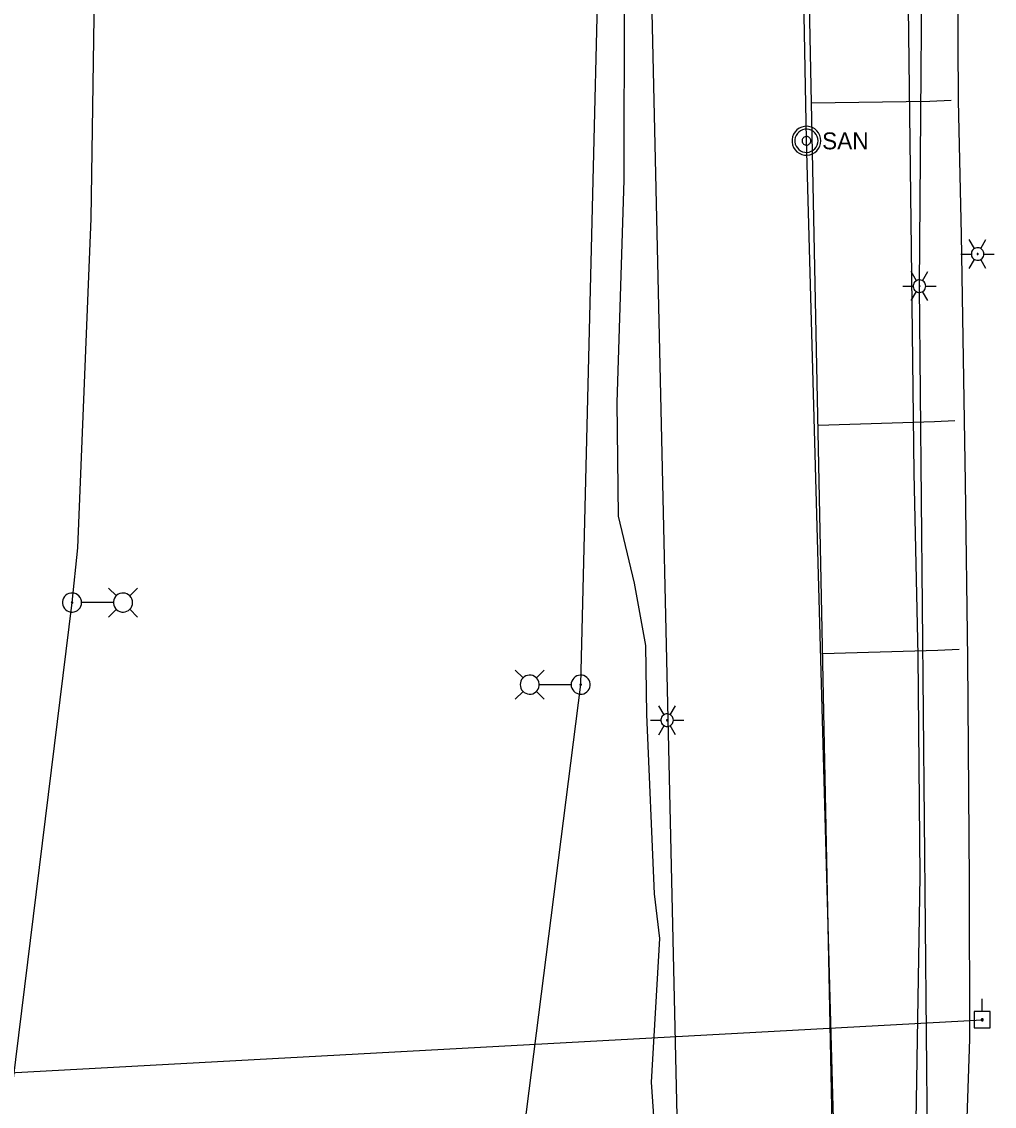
# Model space of a CAD drawing. Extents: x 596028 to 606371, y 330010 to 403088.
# Drawn here: x 604862.3 to 605083.6, y 331870.6 to 332117.3 of the extents above; entities that cross this region are included whole.
import ezdxf

# ---------------------------------------------------------------- set-up
doc = ezdxf.new("R2010")
doc.units = 0
for name, color, linetype in [('E_LTG', 7, 'Continuous'), ('E_LTG_CID', 7, 'Continuous'), ('E_UTL_E_UG', 7, 'Continuous'), ('E_UTL_EPowerPole', 7, 'Continuous'), ('E_UTL_G_UG', 7, 'Continuous'), ('E_UTL_Overhead', 7, 'Continuous'), ('E_UTL_SAN_MH', 7, 'Continuous'), ('E_UTL_SAN_UG', 7, 'Continuous'), ('E_UTL_SAN_UG_MMSD', 7, 'Continuous'), ('E_UTL_W_UG', 7, 'Continuous')]:
    doc.layers.add(name, color=color, linetype=linetype)

msp = doc.modelspace()

# ---------------------------------------------------------------- linework, layer by layer
at = {"layer": 'E_LTG'}
for points in [[(605079.09, 332065.65), (605077.89, 332067.72)], [(605080.51, 332065.65), (605081.71, 332067.72)], [(605075.99, 332064.42), (605078.37, 332064.42)], [(605081.23, 332064.42), (605081.2, 332064.69), (605081.13, 332064.95), (605081, 332065.19), (605080.83, 332065.4), (605080.63, 332065.58), (605080.39, 332065.72), (605080.14, 332065.8), (605079.87, 332065.84), (605079.6, 332065.83), (605079.33, 332065.77), (605079.09, 332065.65), (605078.86, 332065.5), (605078.68, 332065.3), (605078.53, 332065.07), (605078.43, 332064.82), (605078.38, 332064.55), (605078.38, 332064.28), (605078.43, 332064.01), (605078.53, 332063.76), (605078.68, 332063.53), (605078.86, 332063.34), (605079.09, 332063.18), (605079.33, 332063.07), (605079.6, 332063), (605079.87, 332062.99), (605080.14, 332063.03), (605080.39, 332063.12), (605080.63, 332063.25), (605080.83, 332063.43), (605081, 332063.64), (605081.13, 332063.88), (605081.2, 332064.15), (605081.23, 332064.42)], [(605081.23, 332064.42), (605081.2, 332064.69), (605081.13, 332064.95), (605081, 332065.19), (605080.83, 332065.4), (605080.63, 332065.58), (605080.39, 332065.72), (605080.14, 332065.8), (605079.87, 332065.84), (605079.6, 332065.83), (605079.33, 332065.77), (605079.09, 332065.65), (605078.86, 332065.5), (605078.68, 332065.3), (605078.53, 332065.07), (605078.43, 332064.82), (605078.38, 332064.55), (605078.38, 332064.28), (605078.43, 332064.01), (605078.53, 332063.76), (605078.68, 332063.53), (605078.86, 332063.34), (605079.09, 332063.18), (605079.33, 332063.07), (605079.6, 332063), (605079.87, 332062.99), (605080.14, 332063.03), (605080.39, 332063.12), (605080.63, 332063.25), (605080.83, 332063.43), (605081, 332063.64), (605081.13, 332063.88), (605081.2, 332064.15), (605081.23, 332064.42)], [(605081.23, 332064.42), (605081.2, 332064.69), (605081.13, 332064.95), (605081, 332065.19), (605080.83, 332065.4), (605080.63, 332065.58), (605080.39, 332065.72), (605080.14, 332065.8), (605079.87, 332065.84), (605079.6, 332065.83), (605079.33, 332065.77), (605079.09, 332065.65), (605078.86, 332065.5), (605078.68, 332065.3), (605078.53, 332065.07), (605078.43, 332064.82), (605078.38, 332064.55), (605078.38, 332064.28), (605078.43, 332064.01), (605078.53, 332063.76), (605078.68, 332063.53), (605078.86, 332063.34), (605079.09, 332063.18), (605079.33, 332063.07), (605079.6, 332063), (605079.87, 332062.99), (605080.14, 332063.03), (605080.39, 332063.12), (605080.63, 332063.25), (605080.83, 332063.43), (605081, 332063.64), (605081.13, 332063.88), (605081.2, 332064.15), (605081.23, 332064.42)], [(605079.92, 332064.42), (605079.92, 332064.44), (605079.91, 332064.46), (605079.9, 332064.48), (605079.89, 332064.5), (605079.87, 332064.51), (605079.85, 332064.52), (605079.83, 332064.53), (605079.81, 332064.53), (605079.78, 332064.53), (605079.76, 332064.53), (605079.74, 332064.52), (605079.72, 332064.51), (605079.71, 332064.49), (605079.69, 332064.47), (605079.69, 332064.45), (605079.68, 332064.43), (605079.68, 332064.4), (605079.69, 332064.38), (605079.69, 332064.36), (605079.71, 332064.34), (605079.72, 332064.33), (605079.74, 332064.31), (605079.76, 332064.3), (605079.78, 332064.3), (605079.81, 332064.3), (605079.83, 332064.3), (605079.85, 332064.31), (605079.87, 332064.32), (605079.89, 332064.33), (605079.9, 332064.35), (605079.91, 332064.37), (605079.92, 332064.39), (605079.92, 332064.42)], [(605081.23, 332064.42), (605083.61, 332064.42)], [(605077.89, 332061.12), (605079.09, 332063.18)], [(605081.71, 332061.12), (605080.51, 332063.18)], [(605065.87, 332058.34), (605064.67, 332060.41)], [(605068.01, 332057.11), (605067.98, 332057.38), (605067.91, 332057.64), (605067.78, 332057.88), (605067.61, 332058.09), (605067.41, 332058.27), (605067.17, 332058.41), (605066.92, 332058.49), (605066.65, 332058.53), (605066.38, 332058.52), (605066.11, 332058.46), (605065.87, 332058.34), (605065.64, 332058.19), (605065.46, 332057.99), (605065.31, 332057.76), (605065.21, 332057.51), (605065.16, 332057.24), (605065.16, 332056.97), (605065.21, 332056.7), (605065.31, 332056.45), (605065.46, 332056.22), (605065.64, 332056.03), (605065.87, 332055.87), (605066.11, 332055.76), (605066.38, 332055.69), (605066.65, 332055.68), (605066.92, 332055.72), (605067.17, 332055.81), (605067.41, 332055.94), (605067.61, 332056.12), (605067.78, 332056.33), (605067.91, 332056.57), (605067.98, 332056.84), (605068.01, 332057.11)], [(605068.01, 332057.11), (605067.98, 332057.38), (605067.91, 332057.64), (605067.78, 332057.88), (605067.61, 332058.09), (605067.41, 332058.27), (605067.17, 332058.41), (605066.92, 332058.49), (605066.65, 332058.53), (605066.38, 332058.52), (605066.11, 332058.46), (605065.87, 332058.34), (605065.64, 332058.19), (605065.46, 332057.99), (605065.31, 332057.76), (605065.21, 332057.51), (605065.16, 332057.24), (605065.16, 332056.97), (605065.21, 332056.7), (605065.31, 332056.45), (605065.46, 332056.22), (605065.64, 332056.03), (605065.87, 332055.87), (605066.11, 332055.76), (605066.38, 332055.69), (605066.65, 332055.68), (605066.92, 332055.72), (605067.17, 332055.81), (605067.41, 332055.94), (605067.61, 332056.12), (605067.78, 332056.33), (605067.91, 332056.57), (605067.98, 332056.84), (605068.01, 332057.11)], [(605068.01, 332057.11), (605067.98, 332057.38), (605067.91, 332057.64), (605067.78, 332057.88), (605067.61, 332058.09), (605067.41, 332058.27), (605067.17, 332058.41), (605066.92, 332058.49), (605066.65, 332058.53), (605066.38, 332058.52), (605066.11, 332058.46), (605065.87, 332058.34), (605065.64, 332058.19), (605065.46, 332057.99), (605065.31, 332057.76), (605065.21, 332057.51), (605065.16, 332057.24), (605065.16, 332056.97), (605065.21, 332056.7), (605065.31, 332056.45), (605065.46, 332056.22), (605065.64, 332056.03), (605065.87, 332055.87), (605066.11, 332055.76), (605066.38, 332055.69), (605066.65, 332055.68), (605066.92, 332055.72), (605067.17, 332055.81), (605067.41, 332055.94), (605067.61, 332056.12), (605067.78, 332056.33), (605067.91, 332056.57), (605067.98, 332056.84), (605068.01, 332057.11)], [(605067.29, 332058.34), (605068.49, 332060.41)], [(605062.77, 332057.11), (605065.15, 332057.11)], [(605066.7, 332057.11), (605066.7, 332057.13), (605066.69, 332057.15), (605066.68, 332057.17), (605066.67, 332057.19), (605066.65, 332057.2), (605066.63, 332057.21), (605066.61, 332057.22), (605066.59, 332057.22), (605066.56, 332057.22), (605066.54, 332057.22), (605066.52, 332057.21), (605066.5, 332057.2), (605066.49, 332057.18), (605066.47, 332057.16), (605066.47, 332057.14), (605066.46, 332057.12), (605066.46, 332057.09), (605066.47, 332057.07), (605066.47, 332057.05), (605066.49, 332057.03), (605066.5, 332057.02), (605066.52, 332057), (605066.54, 332056.99), (605066.56, 332056.99), (605066.59, 332056.99), (605066.61, 332056.99), (605066.63, 332057), (605066.65, 332057.01), (605066.67, 332057.02), (605066.68, 332057.04), (605066.69, 332057.06), (605066.7, 332057.08), (605066.7, 332057.11)], [(605068.01, 332057.11), (605070.39, 332057.11)], [(605064.67, 332053.81), (605065.87, 332055.87)], [(605068.49, 332053.81), (605067.29, 332055.87)], [(604875.89, 331985.14), (604875.85, 331985.55), (604875.74, 331985.95), (604875.55, 331986.31), (604875.29, 331986.64), (604874.98, 331986.91), (604874.62, 331987.12), (604874.23, 331987.25), (604873.82, 331987.31), (604873.41, 331987.29), (604873, 331987.19), (604872.63, 331987.02), (604872.29, 331986.78), (604872.01, 331986.48), (604871.78, 331986.13), (604871.63, 331985.75), (604871.55, 331985.34), (604871.55, 331984.93), (604871.63, 331984.52), (604871.78, 331984.14), (604872.01, 331983.79), (604872.29, 331983.49), (604872.63, 331983.25), (604873, 331983.08), (604873.41, 331982.98), (604873.82, 331982.96), (604874.23, 331983.02), (604874.62, 331983.16), (604874.98, 331983.36), (604875.29, 331983.64), (604875.55, 331983.96), (604875.74, 331984.33), (604875.85, 331984.73), (604875.89, 331985.14)], [(604883.8, 331986.66), (604882.02, 331988.44)], [(604887.5, 331985.14), (604887.46, 331985.55), (604887.34, 331985.95), (604887.15, 331986.31), (604886.89, 331986.64), (604886.58, 331986.91), (604886.22, 331987.12), (604885.83, 331987.25), (604885.42, 331987.31), (604885.01, 331987.29), (604884.61, 331987.19), (604884.23, 331987.02), (604883.89, 331986.78), (604883.61, 331986.48), (604883.39, 331986.13), (604883.23, 331985.75), (604883.15, 331985.34), (604883.15, 331984.93), (604883.23, 331984.52), (604883.39, 331984.14), (604883.61, 331983.79), (604883.89, 331983.49), (604884.23, 331983.25), (604884.61, 331983.08), (604885.01, 331982.98), (604885.42, 331982.96), (604885.83, 331983.02), (604886.22, 331983.16), (604886.58, 331983.36), (604886.89, 331983.64), (604887.15, 331983.96), (604887.34, 331984.33), (604887.46, 331984.73), (604887.5, 331985.14)], [(604886.84, 331986.66), (604888.62, 331988.44)], [(604873.88, 331985.14), (604873.88, 331985.17), (604873.87, 331985.2), (604873.86, 331985.23), (604873.84, 331985.25), (604873.81, 331985.27), (604873.79, 331985.29), (604873.76, 331985.3), (604873.72, 331985.3), (604873.69, 331985.3), (604873.66, 331985.29), (604873.63, 331985.28), (604873.61, 331985.26), (604873.59, 331985.24), (604873.57, 331985.21), (604873.56, 331985.18), (604873.55, 331985.15), (604873.55, 331985.12), (604873.56, 331985.09), (604873.57, 331985.06), (604873.59, 331985.03), (604873.61, 331985.01), (604873.63, 331984.99), (604873.66, 331984.98), (604873.69, 331984.97), (604873.72, 331984.97), (604873.76, 331984.98), (604873.79, 331984.99), (604873.81, 331985), (604873.84, 331985.02), (604873.86, 331985.05), (604873.87, 331985.08), (604873.88, 331985.11), (604873.88, 331985.14)], [(604883.11, 331985.14), (604875.93, 331985.14)], [(604883.8, 331983.62), (604882.02, 331981.84)], [(604886.84, 331983.62), (604888.62, 331981.84)], [(604976.35, 331967.99), (604974.57, 331969.77)], [(604979.39, 331967.99), (604981.17, 331969.77)], [(604975.7, 331966.47), (604975.74, 331966.06), (604975.85, 331965.66), (604976.04, 331965.29), (604976.3, 331964.97), (604976.61, 331964.69), (604976.97, 331964.49), (604977.36, 331964.35), (604977.77, 331964.29), (604978.18, 331964.31), (604978.58, 331964.41), (604978.96, 331964.58), (604979.3, 331964.82), (604979.58, 331965.12), (604979.81, 331965.47), (604979.96, 331965.85), (604980.04, 331966.26), (604980.04, 331966.67), (604979.96, 331967.08), (604979.81, 331967.46), (604979.58, 331967.81), (604979.3, 331968.11), (604978.96, 331968.35), (604978.58, 331968.52), (604978.18, 331968.62), (604977.77, 331968.64), (604977.36, 331968.58), (604976.97, 331968.45), (604976.61, 331968.24), (604976.3, 331967.97), (604976.04, 331967.64), (604975.85, 331967.28), (604975.74, 331966.88), (604975.7, 331966.47)], [(604987.3, 331966.47), (604987.34, 331966.06), (604987.46, 331965.66), (604987.65, 331965.29), (604987.9, 331964.97), (604988.21, 331964.69), (604988.57, 331964.49), (604988.96, 331964.35), (604989.37, 331964.29), (604989.79, 331964.31), (604990.19, 331964.41), (604990.56, 331964.58), (604990.9, 331964.82), (604991.19, 331965.12), (604991.41, 331965.47), (604991.56, 331965.85), (604991.64, 331966.26), (604991.64, 331966.67), (604991.56, 331967.08), (604991.41, 331967.46), (604991.19, 331967.81), (604990.9, 331968.11), (604990.56, 331968.35), (604990.19, 331968.52), (604989.79, 331968.62), (604989.37, 331968.64), (604988.96, 331968.58), (604988.57, 331968.45), (604988.21, 331968.24), (604987.9, 331967.97), (604987.65, 331967.64), (604987.46, 331967.28), (604987.34, 331966.88), (604987.3, 331966.47)], [(604976.35, 331964.94), (604974.57, 331963.17)], [(604979.39, 331964.94), (604981.17, 331963.17)], [(604980.08, 331966.47), (604987.26, 331966.47)], [(604989.31, 331966.47), (604989.31, 331966.44), (604989.32, 331966.41), (604989.34, 331966.38), (604989.36, 331966.35), (604989.38, 331966.33), (604989.41, 331966.32), (604989.44, 331966.31), (604989.47, 331966.3), (604989.5, 331966.3), (604989.53, 331966.31), (604989.56, 331966.32), (604989.58, 331966.34), (604989.61, 331966.36), (604989.62, 331966.39), (604989.64, 331966.42), (604989.64, 331966.45), (604989.64, 331966.48), (604989.64, 331966.51), (604989.62, 331966.54), (604989.61, 331966.57), (604989.58, 331966.59), (604989.56, 331966.61), (604989.53, 331966.62), (604989.5, 331966.63), (604989.47, 331966.63), (604989.44, 331966.63), (604989.41, 331966.62), (604989.38, 331966.6), (604989.36, 331966.58), (604989.34, 331966.56), (604989.32, 331966.53), (604989.31, 331966.5), (604989.31, 331966.47)], [(605008.44, 331959.61), (605007.24, 331961.68)], [(605010.58, 331958.38), (605010.55, 331958.65), (605010.48, 331958.91), (605010.35, 331959.15), (605010.18, 331959.36), (605009.98, 331959.54), (605009.74, 331959.68), (605009.49, 331959.76), (605009.22, 331959.8), (605008.95, 331959.79), (605008.68, 331959.73), (605008.44, 331959.61), (605008.21, 331959.46), (605008.03, 331959.26), (605007.88, 331959.03), (605007.78, 331958.78), (605007.73, 331958.51), (605007.73, 331958.24), (605007.78, 331957.97), (605007.88, 331957.72), (605008.03, 331957.49), (605008.21, 331957.3), (605008.44, 331957.14), (605008.68, 331957.03), (605008.95, 331956.96), (605009.22, 331956.95), (605009.49, 331956.99), (605009.74, 331957.08), (605009.98, 331957.21), (605010.18, 331957.39), (605010.35, 331957.6), (605010.48, 331957.84), (605010.55, 331958.11), (605010.58, 331958.38)], [(605010.58, 331958.38), (605010.55, 331958.65), (605010.48, 331958.91), (605010.35, 331959.15), (605010.18, 331959.36), (605009.98, 331959.54), (605009.74, 331959.68), (605009.49, 331959.76), (605009.22, 331959.8), (605008.95, 331959.79), (605008.68, 331959.73), (605008.44, 331959.61), (605008.21, 331959.46), (605008.03, 331959.26), (605007.88, 331959.03), (605007.78, 331958.78), (605007.73, 331958.51), (605007.73, 331958.24), (605007.78, 331957.97), (605007.88, 331957.72), (605008.03, 331957.49), (605008.21, 331957.3), (605008.44, 331957.14), (605008.68, 331957.03), (605008.95, 331956.96), (605009.22, 331956.95), (605009.49, 331956.99), (605009.74, 331957.08), (605009.98, 331957.21), (605010.18, 331957.39), (605010.35, 331957.6), (605010.48, 331957.84), (605010.55, 331958.11), (605010.58, 331958.38)], [(605010.58, 331958.38), (605010.55, 331958.65), (605010.48, 331958.91), (605010.35, 331959.15), (605010.18, 331959.36), (605009.98, 331959.54), (605009.74, 331959.68), (605009.49, 331959.76), (605009.22, 331959.8), (605008.95, 331959.79), (605008.68, 331959.73), (605008.44, 331959.61), (605008.21, 331959.46), (605008.03, 331959.26), (605007.88, 331959.03), (605007.78, 331958.78), (605007.73, 331958.51), (605007.73, 331958.24), (605007.78, 331957.97), (605007.88, 331957.72), (605008.03, 331957.49), (605008.21, 331957.3), (605008.44, 331957.14), (605008.68, 331957.03), (605008.95, 331956.96), (605009.22, 331956.95), (605009.49, 331956.99), (605009.74, 331957.08), (605009.98, 331957.21), (605010.18, 331957.39), (605010.35, 331957.6), (605010.48, 331957.84), (605010.55, 331958.11), (605010.58, 331958.38)], [(605009.86, 331959.61), (605011.06, 331961.68)], [(605005.34, 331958.38), (605007.72, 331958.38)], [(605009.27, 331958.38), (605009.27, 331958.4), (605009.26, 331958.42), (605009.25, 331958.44), (605009.24, 331958.46), (605009.22, 331958.47), (605009.2, 331958.48), (605009.18, 331958.49), (605009.16, 331958.5), (605009.13, 331958.49), (605009.11, 331958.49), (605009.09, 331958.48), (605009.07, 331958.47), (605009.06, 331958.45), (605009.04, 331958.43), (605009.04, 331958.41), (605009.03, 331958.39), (605009.03, 331958.36), (605009.04, 331958.34), (605009.04, 331958.32), (605009.06, 331958.3), (605009.07, 331958.29), (605009.09, 331958.27), (605009.11, 331958.26), (605009.13, 331958.26), (605009.16, 331958.26), (605009.18, 331958.26), (605009.2, 331958.27), (605009.22, 331958.28), (605009.24, 331958.29), (605009.25, 331958.31), (605009.26, 331958.33), (605009.27, 331958.35), (605009.27, 331958.38)], [(605010.58, 331958.38), (605012.96, 331958.38)], [(605007.24, 331955.08), (605008.44, 331957.14)], [(605011.06, 331955.08), (605009.86, 331957.14)]]:
    msp.add_lwpolyline(points, dxfattribs=at)
at = {"layer": 'E_LTG_CID'}
for points in [[(604931.85, 331581.07), (604937.27, 331603.67), (604947.8, 331650.94), (604952, 331678.28), (604955.83, 331701.76), (604989.48, 331966.47), (604996.27, 332242.26), (604998.49, 332512.59), (605000.29, 332783.81), (605002.15, 332931.75), (605000.64, 332964.83), (605000.69, 332966.2), (605002.17, 333011.44), (605003.78, 333073.37), (605005.15, 333128.46), (605004.43, 333142.5)], [(604680.92, 331223.31), (604778.52, 331467.17), (604841.28, 331722.49), (604873.72, 331985.14), (604875.05, 331997.61), (604878.05, 332072.5), (604879.01, 332133.59), (604879.29, 332193.85), (604879.03, 332249.73), (604879.6, 332255.02), (604881.21, 332520.43)]]:
    msp.add_lwpolyline(points, dxfattribs=at)
at = {"layer": 'E_UTL_E_UG'}
for points in [[(605060.47, 331707.24), (605067.75, 331788.52), (605068.77, 331809.24), (605068.42, 331863), (605066.58, 332057.11), (605069.29, 332407.59)], [(605038.2, 331558.64), (605053.97, 331665.58), (605054.16, 331675.48), (605057.33, 331710.76), (605063.33, 331779.39), (605064.89, 331811.56), (605066.7, 331922.92), (605066.28, 331973.16), (605065.35, 332014.58), (605064.76, 332065.68), (605063.4, 332175.3), (605062.74, 332212.21)]]:
    msp.add_lwpolyline(points, dxfattribs=at)
at = {"layer": 'E_UTL_EPowerPole'}
for points in [[(605080.84, 331892.08), (605080.84, 331894.99)], [(605082.68, 331892.08), (605078.99, 331892.08)], [(605078.99, 331892.08), (605078.99, 331888.39)], [(605082.68, 331888.39), (605082.68, 331892.08)], [(605078.99, 331888.39), (605082.68, 331888.39)], [(605081.11, 331890.24), (605081.1, 331890.28), (605081.09, 331890.33), (605081.07, 331890.37), (605081.04, 331890.4), (605081.01, 331890.43), (605080.97, 331890.46), (605080.93, 331890.47), (605080.88, 331890.48), (605080.84, 331890.48), (605080.79, 331890.46), (605080.75, 331890.45), (605080.71, 331890.42), (605080.68, 331890.39), (605080.66, 331890.35), (605080.64, 331890.31), (605080.63, 331890.26), (605080.63, 331890.22), (605080.64, 331890.17), (605080.66, 331890.13), (605080.68, 331890.09), (605080.71, 331890.06), (605080.75, 331890.03), (605080.79, 331890.01), (605080.84, 331890), (605080.88, 331890), (605080.93, 331890.01), (605080.97, 331890.02), (605081.01, 331890.04), (605081.04, 331890.07), (605081.07, 331890.11), (605081.09, 331890.15), (605081.1, 331890.19), (605081.11, 331890.24)]]:
    msp.add_lwpolyline(points, dxfattribs=at)
at = {"layer": 'E_UTL_G_UG'}
for points in [[(605007.31, 331850.72), (605005.56, 331876.01), (605007.48, 331908.74), (605006.3, 331918.91), (605004.52, 331959.64), (605004.31, 331975.38), (605001.7, 331989.52), (604998.09, 332004.76), (604997.79, 332030.63), (604999.36, 332081.19), (604999.44, 332122.97), (604998.29, 332157.96), (604998.1, 332193), (604999.13, 332234.39)], [(605030.78, 331483.16), (605036.41, 331510.46), (605041, 331526.42), (605043.91, 331546.77), (605047.79, 331567.91), (605052.35, 331587.01), (605059.28, 331633.75), (605064.76, 331677.5), (605068.49, 331707.7), (605074.22, 331781.45), (605075.46, 331809.71), (605078.06, 331885.79), (605077.96, 331921.74), (605077.56, 331972.3), (605077.08, 332012.55), (605076.17, 332068.78), (605075.45, 332099.34), (605075.08, 332165.21), (605074.66, 332210.44), (605074.75, 332235.8)]]:
    msp.add_lwpolyline(points, dxfattribs=at)
at = {"layer": 'E_UTL_Overhead'}
msp.add_lwpolyline([(604656.35, 331879.77), (604755.8, 331874.8), (604816.26, 331875.81), (605080.87, 331890.24)], dxfattribs=at)
at = {"layer": 'E_UTL_SAN_MH'}
for points in [[(605044.15, 332090.18), (605044.09, 332090.8), (605043.92, 332091.4), (605043.63, 332091.96), (605043.24, 332092.45), (605042.77, 332092.87), (605042.22, 332093.18), (605041.63, 332093.38), (605041.01, 332093.47), (605040.38, 332093.44), (605039.77, 332093.3), (605039.2, 332093.03), (605038.69, 332092.67), (605038.26, 332092.22), (605037.92, 332091.69), (605037.69, 332091.11), (605037.57, 332090.49), (605037.57, 332089.86), (605037.69, 332089.25), (605037.92, 332088.66), (605038.26, 332088.14), (605038.69, 332087.68), (605039.2, 332087.32), (605039.77, 332087.06), (605040.38, 332086.91), (605041.01, 332086.88), (605041.63, 332086.97), (605042.22, 332087.18), (605042.77, 332087.49), (605043.24, 332087.9), (605043.63, 332088.39), (605043.92, 332088.95), (605044.09, 332089.55), (605044.15, 332090.18)], [(605043.49, 332090.18), (605043.44, 332090.68), (605043.3, 332091.16), (605043.07, 332091.6), (605042.76, 332092), (605042.38, 332092.33), (605041.95, 332092.58), (605041.47, 332092.74), (605040.98, 332092.81), (605040.48, 332092.79), (605039.99, 332092.67), (605039.53, 332092.46), (605039.12, 332092.17), (605038.78, 332091.81), (605038.51, 332091.39), (605038.32, 332090.92), (605038.22, 332090.43), (605038.22, 332089.93), (605038.32, 332089.43), (605038.51, 332088.97), (605038.78, 332088.55), (605039.12, 332088.18), (605039.53, 332087.89), (605039.99, 332087.68), (605040.48, 332087.56), (605040.98, 332087.54), (605041.47, 332087.61), (605041.95, 332087.78), (605042.38, 332088.03), (605042.76, 332088.36), (605043.07, 332088.75), (605043.3, 332089.2), (605043.44, 332089.68), (605043.49, 332090.18)], [(605041.84, 332090.18), (605041.82, 332090.36), (605041.77, 332090.54), (605041.68, 332090.71), (605041.57, 332090.86), (605041.43, 332090.98), (605041.26, 332091.08), (605041.08, 332091.14), (605040.9, 332091.17), (605040.71, 332091.16), (605040.53, 332091.11), (605040.36, 332091.03), (605040.2, 332090.93), (605040.07, 332090.79), (605039.97, 332090.63), (605039.9, 332090.46), (605039.87, 332090.27), (605039.87, 332090.08), (605039.9, 332089.9), (605039.97, 332089.72), (605040.07, 332089.56), (605040.2, 332089.43), (605040.36, 332089.32), (605040.53, 332089.24), (605040.71, 332089.2), (605040.9, 332089.19), (605041.08, 332089.21), (605041.26, 332089.28), (605041.43, 332089.37), (605041.57, 332089.49), (605041.68, 332089.64), (605041.77, 332089.81), (605041.82, 332089.99), (605041.84, 332090.18)]]:
    msp.add_lwpolyline(points, dxfattribs=at)
at = {"layer": 'E_UTL_SAN_UG'}
for p, q in [((605040.9, 332090.37), (605035.68, 332357.68)), ((605048.95, 331795.33), (605040.9, 332090.37))]:
    msp.add_line(p, q, dxfattribs=at)
at = {"layer": 'E_UTL_SAN_UG_MMSD'}
msp.add_line((605012.41, 331824.88), (605001.66, 332297.25), dxfattribs=at)
at = {"layer": 'E_UTL_W_UG'}
for points in [[(604662.85, 330776.78), (604719.99, 330861.17), (604771.51, 330900.13), (604792.62, 330926.22), (604804.59, 330947.13), (605054.68, 331381.7), (605055.13, 331442.45), (605044.65, 331474.36), (605047.01, 331851.63), (605038.36, 332278.66), (605035.8, 332410.28), (605072.23, 332411.32), (605076.98, 332411.12), (605079.88, 332411.16)], [(605042, 332098.82), (605068.96, 332099.21), (605073.81, 332099.42)], [(605043.49, 332025.51), (605070.01, 332026.3), (605074.66, 332026.58)], [(605044.54, 331973.56), (605070.79, 331974.34), (605075.61, 331974.52)]]:
    msp.add_lwpolyline(points, dxfattribs=at)

# ---------------------------------------------------------------- texts
at = {"layer": 'E_UTL_SAN_MH'}
msp.add_text('SAN', height=3.849, dxfattribs=at).set_placement((605044.42, 332088.23))

doc.saveas('drawing.dxf')
